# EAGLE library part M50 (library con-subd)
SUB-D
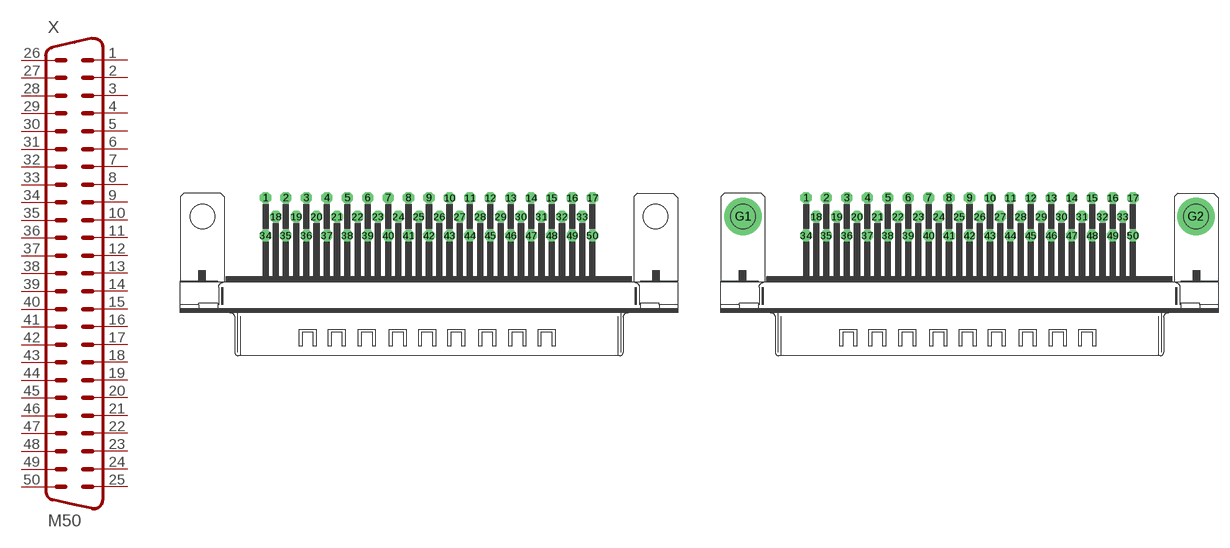
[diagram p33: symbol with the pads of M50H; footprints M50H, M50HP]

Designator prefix X

## M50H (OC_FARNELL: unknown; OC_NEWARK: unknown)  [M50H]
1  1  pas
2  2  pas
3  3  pas
4  4  pas
5  5  pas
6  6  pas
7  7  pas
8  8  pas
9  9  pas
10  10  pas
11  11  pas
12  12  pas
13  13  pas
14  14  pas
15  15  pas
16  16  pas
17  17  pas
18  18  pas
19  19  pas
20  20  pas
21  21  pas
22  22  pas
23  23  pas
24  24  pas
25  25  pas
26  26  pas
27  27  pas
28  28  pas
29  29  pas
30  30  pas
31  31  pas
32  32  pas
33  33  pas
34  34  pas
35  35  pas
36  36  pas
37  37  pas
38  38  pas
39  39  pas
40  40  pas
41  41  pas
42  42  pas
43  43  pas
44  44  pas
45  45  pas
46  46  pas
47  47  pas
48  48  pas
49  49  pas
50  50  pas

## M50HP (OC_FARNELL: unknown; OC_NEWARK: unknown)  [M50HP]
Pads as for M50H

## M50V (OC_FARNELL: unknown; OC_NEWARK: unknown)  [M50V]
Pads as for M50H

## M50VP (OC_FARNELL: unknown; OC_NEWARK: unknown)  [M50VP]
Pads as for M50H

## M50VB (OC_FARNELL: unknown; OC_NEWARK: unknown)  [M50VB]
Pads as for M50H

## Footprint M50H (pad centres in mm)
SUB-D
drill 1.016 octagon: 1 -22.073,2.54; 2 -19.329,2.54; 3 -16.561,2.54; 4 -13.792,2.54; 5 -11.049,2.54; 6 -8.28,2.54; 7 -5.512,2.54; 8 -2.769,2.54; 9 0,2.54; 10 2.769,2.54; 11 5.512,2.54; 12 8.28,2.54; 13 11.049,2.54; 14 13.792,2.54; 15 16.561,2.54; 16 19.329,2.54; 17 22.073,2.54; 18 -20.701,0; 19 -17.932,0; 20 -15.189,0; 21 -12.421,0; 22 -9.652,0; 23 -6.883,0; 24 -4.14,0; 25 -1.372,0; 26 1.397,0; 27 4.14,0; 28 6.909,0; 29 9.677,0; 30 12.421,0; 31 15.189,0; 32 17.958,0; 33 20.701,0; 34 -22.073,-2.54; 35 -19.329,-2.54; 36 -16.561,-2.54; 37 -13.792,-2.54; 38 -11.049,-2.54; 39 -8.28,-2.54; 40 -5.512,-2.54; 41 -2.769,-2.54; 42 0,-2.54; 43 2.769,-2.54; 44 5.512,-2.54; 45 8.28,-2.54; 46 11.049,-2.54; 47 13.792,-2.54; 48 16.561,-2.54; 49 19.329,-2.54; 50 22.073,-2.54
hole 3.302 at 30.556,0
hole 3.302 at -30.556,0

## Footprint M50HP (pad centres in mm)
SUB-D
drill 1.016 octagon: 1 -22.073,2.54; 2 -19.329,2.54; 3 -16.561,2.54; 4 -13.792,2.54; 5 -11.049,2.54; 6 -8.28,2.54; 7 -5.512,2.54; 8 -2.769,2.54; 9 0,2.54; 10 2.769,2.54; 11 5.512,2.54; 12 8.28,2.54; 13 11.049,2.54; 14 13.792,2.54; 15 16.561,2.54; 16 19.329,2.54; 17 22.073,2.54; 18 -20.701,0; 19 -17.932,0; 20 -15.189,0; 21 -12.421,0; 22 -9.652,0; 23 -6.883,0; 24 -4.14,0; 25 -1.372,0; 26 1.397,0; 27 4.14,0; 28 6.909,0; 29 9.677,0; 30 12.421,0; 31 15.189,0; 32 17.958,0; 33 20.701,0; 34 -22.073,-2.54; 35 -19.329,-2.54; 36 -16.561,-2.54; 37 -13.792,-2.54; 38 -11.049,-2.54; 39 -8.28,-2.54; 40 -5.512,-2.54; 41 -2.769,-2.54; 42 0,-2.54; 43 2.769,-2.54; 44 5.512,-2.54; 45 8.28,-2.54; 46 11.049,-2.54; 47 13.792,-2.54; 48 16.561,-2.54; 49 19.329,-2.54; 50 22.073,-2.54
drill 3.302 pad 5.08 round: G1 -30.556,0; G2 30.556,0

## Footprint M50V (pad centres in mm)
SUB-D
drill 1.016 octagon: 1 -22.073,2.845; 2 -19.329,2.845; 3 -16.561,2.845; 4 -13.792,2.845; 5 -11.049,2.845; 6 -8.28,2.845; 7 -5.512,2.845; 8 -2.769,2.845; 9 0,2.845; 10 2.769,2.845; 11 5.512,2.845; 12 8.28,2.845; 13 11.049,2.845; 14 13.792,2.845; 15 16.561,2.845; 16 19.329,2.845; 17 22.073,2.845; 18 -20.701,0; 19 -17.932,0; 20 -15.189,0; 21 -12.421,0; 22 -9.652,0; 23 -6.909,0; 24 -4.14,0; 25 -1.372,0; 26 1.372,0; 27 4.14,0; 28 6.909,0; 29 9.652,0; 30 12.421,0; 31 15.189,0; 32 17.932,0; 33 20.701,0; 34 -22.073,-2.845; 35 -19.329,-2.845; 36 -16.561,-2.845; 37 -13.792,-2.845; 38 -11.049,-2.845; 39 -8.28,-2.845; 40 -5.512,-2.845; 41 -2.769,-2.845; 42 0,-2.845; 43 2.769,-2.845; 44 5.512,-2.845; 45 8.28,-2.845; 46 11.049,-2.845; 47 13.792,-2.845; 48 16.561,-2.845; 49 19.329,-2.845; 50 22.073,-2.845
hole 3.302 at 30.556,0
hole 3.302 at -30.556,0

## Footprint M50VP (pad centres in mm)
SUB-D
drill 1.016 octagon: 1 -22.073,2.845; 2 -19.329,2.845; 3 -16.561,2.845; 4 -13.792,2.845; 5 -11.049,2.845; 6 -8.28,2.845; 7 -5.512,2.845; 8 -2.769,2.845; 9 0,2.845; 10 2.769,2.845; 11 5.512,2.845; 12 8.28,2.845; 13 11.049,2.845; 14 13.792,2.845; 15 16.561,2.845; 16 19.329,2.845; 17 22.073,2.845; 18 -20.701,0; 19 -17.932,0; 20 -15.189,0; 21 -12.421,0; 22 -9.652,0; 23 -6.909,0; 24 -4.14,0; 25 -1.372,0; 26 1.372,0; 27 4.14,0; 28 6.909,0; 29 9.652,0; 30 12.421,0; 31 15.189,0; 32 17.932,0; 33 20.701,0; 34 -22.073,-2.845; 35 -19.329,-2.845; 36 -16.561,-2.845; 37 -13.792,-2.845; 38 -11.049,-2.845; 39 -8.28,-2.845; 40 -5.512,-2.845; 41 -2.769,-2.845; 42 0,-2.845; 43 2.769,-2.845; 44 5.512,-2.845; 45 8.28,-2.845; 46 11.049,-2.845; 47 13.792,-2.845; 48 16.561,-2.845; 49 19.329,-2.845; 50 22.073,-2.845
drill 3.302 pad 5.08 round: G1 -30.556,0; G2 30.556,0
